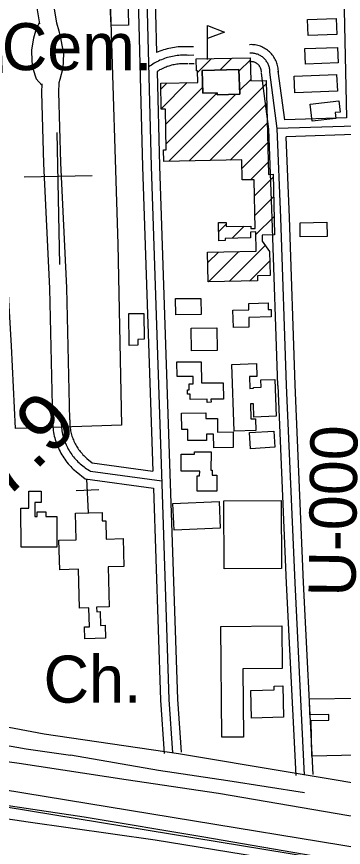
# Model space of a CAD drawing. Extents: x 3508733 to 3546731, y 546897 to 572481.
# Drawn here: x 3525061 to 3525636, y 566055 to 567520 of the extents above; entities that cross this region are included whole.
import ezdxf

# ---------------------------------------------------------------- set-up
doc = ezdxf.new("R2010")
doc.units = 0
for name, color, linetype in [('V-BLDG-OTLN', 7, 'Continuous'), ('V-FLOD-BASE', 7, 'Continuous'), ('V-LEVE-TOET', 7, 'Continuous'), ('V-RIVR-RANG-IDEN', 7, 'Continuous'), ('V-ROAD-CNTR', 7, 'Continuous'), ('V-SITE-OTLN', 7, 'Continuous'), ('V-SITE-OTLN-IDEN', 7, 'Continuous'), ('V-SURV-IDEN', 7, 'Continuous'), ('V-SURV-LINE', 7, 'Continuous'), ('V-TOPO-SHOR', 7, 'Continuous')]:
    doc.layers.add(name, color=color, linetype=linetype)

msp = doc.modelspace()

# ---------------------------------------------------------------- linework, layer by layer
at = {"layer": 'V-BLDG-OTLN'}
for p, q in [((3525397.2, 567444.3), (3525396.9, 567504.3)), ((3525379.4, 567421.6), (3525404, 567446.2)), ((3525419.2, 567426.1), (3525440.1, 567446.9)), ((3525452.5, 567424), (3525472.5, 567444)), ((3525453.5, 567389.6), (3525473.2, 567409.4)), ((3525314.7, 567392.3), (3525325.4, 567402.9)), ((3525315.4, 567357.6), (3525361.4, 567403.7)), ((3525323.3, 567330.1), (3525388.4, 567395.3)), ((3525364.8, 567265.6), (3525500.5, 567401.3)), ((3525324, 567295.5), (3525414.1, 567385.6)), ((3525328.7, 567264.9), (3525447.2, 567383.4)), ((3525400.9, 567266.3), (3525501.4, 567366.8)), ((3525437, 567267), (3525502.3, 567332.3)), ((3525457.8, 567252.5), (3525503.1, 567297.9)), ((3525472.9, 567232.3), (3525504, 567263.4)), ((3525479.9, 567203.9), (3525512.6, 567236.7)), ((3525480.6, 567169.3), (3525513.5, 567202.2)), ((3525482.3, 567135.6), (3525514.4, 567167.7)), ((3525416.8, 567140.8), (3525430.1, 567154.1)), ((3525440.4, 567129.1), (3525461.8, 567150.4)), ((3525434.9, 567052.8), (3525498.7, 567116.6)), ((3525397.5, 567086.2), (3525416.3, 567104.9)), ((3525398.8, 567052.1), (3525452.3, 567105.6)), ((3525470.9, 567053.5), (3525506.8, 567089.4))]:
    msp.add_line(p, q, dxfattribs=at)
for points in [[(3525222.6, 567601.8), (3525262.3, 567602.9), (3525262.9, 567580.8), (3525255.9, 567580.6), (3525258, 567505.1), (3525227.2, 567504.3)], [(3525624.7, 567488.8), (3525574.5, 567487), (3525573.5, 567515.1), (3525623.7, 567516.9)], [(3525396.9, 567504.3), (3525426.9, 567492.9), (3525397, 567481.2)], [(3525627, 567438.5), (3525569.6, 567436.3), (3525568.6, 567463.7), (3525626, 567465.9)], [(3525500.4, 567407.4), (3525504.6, 567241.9), (3525512.5, 567242.1), (3525515.2, 567135.3), (3525493.2, 567134.7), (3525493.5, 567123.8), (3525506.5, 567105.8), (3525507.4, 567063.2), (3525484.9, 567062.8), (3525485.1, 567053.8), (3525398.2, 567052.1), (3525397.1, 567104.6), (3525482.9, 567106.3), (3525482.2, 567140.2), (3525472.7, 567140), (3525472.9, 567129.7), (3525428.4, 567128.8), (3525428.4, 567125.1), (3525417.1, 567124.8), (3525416.5, 567156.7), (3525430, 567157), (3525430.1, 567149.8), (3525473.4, 567150.7), (3525473.5, 567146.5), (3525481.1, 567146.6), (3525479.3, 567232.4), (3525458.2, 567232), (3525457.5, 567267.5), (3525319.9, 567264.7), (3525319.5, 567285.1), (3525324.2, 567285.2), (3525322.8, 567356.8), (3525315.4, 567356.7), (3525314.5, 567402.7), (3525379.7, 567404), (3525379.3, 567424.3), (3525377.4, 567424.2), (3525376.9, 567445.7), (3525472.4, 567447.6), (3525473.3, 567406.8)], [(3525387.5, 567425.1), (3525388.7, 567384.9), (3525414.1, 567385.7), (3525414.2, 567382.4), (3525453.7, 567383.5), (3525452.4, 567427)], [(3525387.5, 567425.1), (3525452.4, 567427), (3525453.7, 567383.5), (3525414.2, 567382.4), (3525414.1, 567385.7), (3525388.7, 567384.9)], [(3525625.8, 567388.4), (3525550.7, 567385.5), (3525549.6, 567415.3), (3525624.6, 567418.1)], [(3525623.2, 567340.5), (3525581.7, 567335.5), (3525578.1, 567365.8), (3525628.5, 567371.8), (3525630.9, 567351.7), (3525622, 567350.7)], [(3525607.8, 567132.4), (3525560.4, 567131.6), (3525560, 567156.5), (3525607.4, 567157.3)], [(3525385.7, 566994.6), (3525341.1, 566994.3), (3525340.9, 567022.7), (3525385.5, 567023)], [(3525509.4, 566990.3), (3525469.7, 566989.2), (3525470.1, 566972.5), (3525442.8, 566971.8), (3525441.9, 567002.1), (3525470, 567002.9), (3525469.7, 567014.3), (3525503.7, 567015.3), (3525504.1, 567003.3), (3525509, 567003.4)], [(3525258.4, 566996.4), (3525285.1, 566996.7), (3525285.5, 566950.9), (3525274.1, 566950.8), (3525274.2, 566940.3), (3525259, 566940.1)], [(3525413.4, 566971.3), (3525414, 566931.3), (3525368.9, 566930.6), (3525368.3, 566970.6)], [(3525386.3, 566874), (3525424.7, 566874.4), (3525425, 566845.5), (3525403.1, 566845.3), (3525403.2, 566839.8), (3525396.3, 566839.7), (3525396.2, 566845.2), (3525366.4, 566844.9), (3525366.3, 566854), (3525361.9, 566853.9), (3525361.8, 566861.9), (3525364.7, 566862), (3525364.6, 566872.4), (3525372, 566872.5), (3525371.9, 566885.4), (3525343.4, 566885.1), (3525343.1, 566911), (3525385.9, 566911.4)], [(3525439.6, 566906.7), (3525483.2, 566908.4), (3525484, 566885.5), (3525471, 566885.1), (3525471.8, 566864.4), (3525478.3, 566864.6), (3525478.3, 566866.1), (3525491.5, 566866.6), (3525491, 566879.2), (3525515.7, 566880.1), (3525518.1, 566815.2), (3525478.7, 566813.8), (3525477.8, 566837), (3525472.6, 566836.8), (3525473.6, 566810.5), (3525481.5, 566810.8), (3525482.2, 566790.3), (3525444, 566788.8)], [(3525395.2, 566772.7), (3525362.4, 566772.3), (3525362.2, 566792.1), (3525351.5, 566791.9), (3525351.1, 566820.5), (3525394.1, 566821.1), (3525394.3, 566811), (3525414.4, 566811.2), (3525414.7, 566787.3), (3525442, 566787.6), (3525442.4, 566760), (3525408, 566759.5), (3525407.6, 566783.7), (3525395.1, 566783.5)], [(3525471.2, 566786.3), (3525514, 566788.9), (3525515.7, 566760.4), (3525472.9, 566757.7)], [(3525383.2, 566718.1), (3525350.6, 566718.1), (3525350.7, 566748.5), (3525374, 566748.5), (3525374, 566752.4), (3525403.2, 566752.3), (3525403.1, 566719.9), (3525405.4, 566719.9), (3525405.4, 566711.1), (3525413.3, 566711.1), (3525413.2, 566683), (3525378.5, 566683), (3525378.6, 566709.9), (3525383.1, 566709.9)], [(3525131.4, 566584.4), (3525068.4, 566584.2), (3525068.2, 566652.8), (3525082.1, 566652.8), (3525082, 566683.2), (3525103.9, 566683.2), (3525103.9, 566662.8), (3525092.5, 566662.8), (3525092.5, 566638.3), (3525096.6, 566638.3), (3525096.6, 566646.7), (3525112.3, 566646.7), (3525112.3, 566638.6), (3525131.3, 566638.6)], [(3525419.6, 566617.6), (3525338, 566614.1), (3525336, 566661.4), (3525417.6, 566664.9)], [(3525426.6, 566545.9), (3525425.8, 566666), (3525526.6, 566666.7), (3525527.5, 566546.6)], [(3525171.3, 566476.8), (3525169.4, 566545.2), (3525136.6, 566544.3), (3525135.2, 566596.4), (3525165.8, 566597.3), (3525164.5, 566644.5), (3525211.2, 566645.7), (3525211.6, 566630.6), (3525217.8, 566630.7), (3525218.7, 566598.5), (3525248.1, 566599.3), (3525249.4, 566550.3), (3525222, 566549.6), (3525223.9, 566479.1), (3525201.5, 566478.5), (3525201.8, 566470.3), (3525207.8, 566470.5), (3525208.5, 566446.1), (3525216.9, 566446.4), (3525217.5, 566423.7), (3525180.7, 566422.7), (3525180.1, 566443.8), (3525188.9, 566444), (3525188, 566477.2)], [(3525420.3, 566444.6), (3525528, 566445.5), (3525528.7, 566370), (3525459.5, 566369.4), (3525460.5, 566249.4), (3525422.1, 566249)], [(3525659.7, 566217.1), (3525580.7, 566215.9), (3525579.8, 566278.6), (3525610.8, 566279.1), (3525610.7, 566289.1), (3525577.4, 566288.6), (3525577, 566316.5), (3525665.4, 566317.9), (3525664.9, 566351.9), (3525680.9, 566352.2), (3525681.2, 566333.6), (3525692.9, 566333.8), (3525693.6, 566290.3), (3525683.3, 566290.1), (3525683.3, 566287.4), (3525666.9, 566287.2), (3525666.9, 566291.4), (3525658.5, 566291.2)], [(3525531.2, 566284.3), (3525474.3, 566282.8), (3525473.1, 566331.4), (3525514.5, 566332.4), (3525514.3, 566339.2), (3525529.8, 566339.6)]]:
    msp.add_lwpolyline(points, close=True, dxfattribs=at)
at = {"layer": 'V-FLOD-BASE'}
msp.add_lwpolyline([(3527002.6, 565995.7), (3526928.9, 566006.7), (3526890.6, 566009.2), (3526863.9, 566009.4), (3526827.7, 566007.1), (3526794.8, 566000.6), (3526742.7, 565989.5), (3526684.4, 565970.3), (3526606.1, 565938.2), (3526534.1, 565910.9), (3526495.6, 565894.9), (3526466.9, 565891.1), (3526442.9, 565890), (3526394.5, 565901.4), (3526294.9, 565918.8), (3526170, 565939.2), (3526009.6, 565966.9), (3525802.8, 566002.5), (3525581.7, 566039.6), (3525390.6, 566073), (3525179.7, 566107.9), (3524998.1, 566135.1), (3524872.1, 566156.4)], dxfattribs=at)
at = {"layer": 'V-LEVE-TOET'}
msp.add_line((3524916.6, 566224.7), (3525065.2, 566203.2), dxfattribs=at)
for points in [[(3525065.2, 566203.2), (3525253.6, 566174.6), (3525416.1, 566150.4), (3525646.1, 566111.1), (3525859.8, 566078.2), (3526102.7, 566038.1), (3526328.6, 565997.6), (3526390.1, 565989.4), (3526435.9, 565988.9), (3526487.9, 565995.9), (3526511.2, 566001.2), (3526586, 566023.6), (3526725.9, 566073.5), (3526776.7, 566087.3), (3526828.7, 566095), (3526897.8, 566101.1)], [(3524899.4, 566127), (3525081, 566099.9), (3525304.9, 566068.2), (3525485.1, 566038.4)]]:
    msp.add_lwpolyline(points, dxfattribs=at)
at = {"layer": 'V-ROAD-CNTR'}
for points in [[(3525626.5, 568407.7), (3525646.7, 567804), (3525657.4, 567327.1), (3525520, 567322.8)], [(3525612, 568391.9), (3525631.7, 567803.6), (3525642.1, 567341.6), (3525533.1, 567338.2)], [(3525265.1, 567832.3), (3525271.9, 567664.4), (3525282.6, 567255.2), (3525300.7, 566718.5)], [(3525280.1, 567833), (3525286.9, 567664.9), (3525297.6, 567255.6), (3525316.4, 566696.1), (3525328.9, 566315.3), (3525335.5, 566221.3)], [(3525295.1, 567833.6), (3525301.9, 567665.4), (3525307.3, 567456.9)], [(3525125.8, 567540.4), (3525130.7, 567509.3), (3525135.3, 567495.3), (3525138.8, 567479.1), (3525143, 567454.6), (3525141.9, 567429.4), (3525136.5, 567409.2), (3525134.9, 567403.5), (3525134.7, 567386.7), (3525138.2, 567262.3), (3525148.3, 567041.5), (3525154, 566808.6)], [(3525096.1, 567535.7), (3525100.7, 567507.2)], [(3525100.4, 567508.3), (3525095.2, 567498.6), (3525090.2, 567481.9), (3525086.9, 567461.7), (3525087.5, 567441.1), (3525089, 567428.6), (3525095.2, 567410.3), (3525105.2, 567399.4)], [(3525364.9, 567466.7), (3525361.8, 567466.9), (3525358.5, 567467), (3525355.2, 567467), (3525351.9, 567467), (3525348.6, 567466.8), (3525345.3, 567466.6), (3525342, 567466.2), (3525338.7, 567465.8), (3525335.5, 567465.3), (3525332.2, 567464.7), (3525329, 567464), (3525325.8, 567463.2), (3525322.6, 567462.3), (3525319.4, 567461.4), (3525316.3, 567460.3), (3525313.2, 567459.2), (3525307.3, 567456.9)], [(3525372.2, 567467), (3525363.4, 567466.7)], [(3525522, 567422.3), (3525521.9, 567424.3), (3525521.8, 567426.7), (3525521.5, 567429), (3525521.1, 567431.4), (3525520.6, 567433.7), (3525520, 567436), (3525519.3, 567438.2), (3525518.4, 567440.4), (3525517.5, 567442.6), (3525516.4, 567444.7), (3525515.3, 567446.8), (3525514, 567448.8), (3525512.7, 567450.8), (3525511.2, 567452.6), (3525509.7, 567454.5), (3525508.1, 567456.2), (3525506.4, 567457.8), (3525504.6, 567459.4), (3525502.7, 567460.9), (3525500.8, 567462.3), (3525498.8, 567463.5), (3525496.8, 567464.7), (3525494.7, 567465.8), (3525492.5, 567466.8), (3525490.3, 567467.7), (3525488.1, 567468.4), (3525485.8, 567469.1), (3525483.5, 567469.6), (3525481.2, 567470.1), (3525478.8, 567470.4), (3525476.5, 567470.6), (3525474.1, 567470.7), (3525471.8, 567470.6), (3525471, 567470.6)], [(3525363.9, 567451.7), (3525361, 567451.9), (3525358.2, 567452), (3525355.3, 567452), (3525352.4, 567452), (3525349.5, 567451.9), (3525346.6, 567451.6), (3525343.7, 567451.3), (3525340.9, 567451), (3525338, 567450.5), (3525335.2, 567450), (3525332.4, 567449.4), (3525329.6, 567448.7), (3525326.8, 567447.9), (3525324, 567447.1), (3525321.3, 567446.2), (3525318.6, 567445.2), (3525315.9, 567444.1), (3525313.2, 567443), (3525310.6, 567441.8), (3525308, 567440.5), (3525305.5, 567439.1), (3525302.9, 567437.7), (3525300.5, 567436.2), (3525298.1, 567434.6), (3525295.7, 567433), (3525293.3, 567431.3), (3525293, 567431)], [(3525372.8, 567452), (3525363.9, 567451.7)], [(3525507, 567422), (3525506.9, 567423.7), (3525506.8, 567425.3), (3525506.6, 567426.9), (3525506.4, 567428.5), (3525506, 567430.1), (3525505.6, 567431.7), (3525505.1, 567433.3), (3525504.5, 567434.8), (3525503.9, 567436.3), (3525503.1, 567437.8), (3525502.3, 567439.2), (3525501.5, 567440.6), (3525500.5, 567441.9), (3525499.6, 567443.2), (3525498.5, 567444.5), (3525497.4, 567445.7), (3525496.2, 567446.8), (3525495, 567447.9), (3525493.7, 567448.9), (3525492.4, 567449.9), (3525491, 567450.7), (3525489.6, 567451.6), (3525488.1, 567452.3), (3525486.6, 567453), (3525485.1, 567453.6), (3525483.6, 567454.1), (3525482, 567454.6), (3525480.4, 567454.9), (3525478.8, 567455.2), (3525477.2, 567455.5), (3525475.6, 567455.6), (3525473.9, 567455.7), (3525472.3, 567455.6), (3525471.7, 567455.6)], [(3525363, 567436.8), (3525360.3, 567436.9), (3525357.8, 567437), (3525355.3, 567437), (3525352.9, 567437), (3525350.4, 567436.9), (3525347.9, 567436.7), (3525345.5, 567436.4), (3525343, 567436.1), (3525340.6, 567435.7), (3525338.1, 567435.3), (3525335.7, 567434.8), (3525333.3, 567434.2), (3525330.9, 567433.5), (3525328.6, 567432.8), (3525326.2, 567432), (3525323.9, 567431.2), (3525321.6, 567430.2), (3525319.3, 567429.3), (3525317.1, 567428.2), (3525314.9, 567427.1), (3525312.7, 567426), (3525310.5, 567424.7), (3525308.2, 567423.3)], [(3525373.3, 567437.1), (3525364.5, 567436.7)], [(3525492, 567421.8), (3525491.9, 567423), (3525491.9, 567423.9), (3525491.8, 567424.8), (3525491.6, 567425.7), (3525491.4, 567426.6), (3525491.2, 567427.5), (3525490.9, 567428.3), (3525490.6, 567429.2), (3525490.3, 567430), (3525489.9, 567430.8), (3525489.4, 567431.6), (3525488.9, 567432.3), (3525488.4, 567433.1), (3525487.9, 567433.8), (3525487.3, 567434.5), (3525486.7, 567435.1), (3525486, 567435.8), (3525485.4, 567436.4), (3525484.7, 567436.9), (3525483.9, 567437.5), (3525483.2, 567437.9), (3525482.4, 567438.4), (3525481.6, 567438.8), (3525480.8, 567439.2), (3525479.9, 567439.5), (3525479.1, 567439.8), (3525478.2, 567440.1), (3525477.3, 567440.3), (3525476.4, 567440.4), (3525475.6, 567440.5), (3525474.7, 567440.6), (3525473.8, 567440.7), (3525472.7, 567440.6), (3525472.4, 567440.6)], [(3525308.2, 567423.3), (3525312.6, 567256.1), (3525331.4, 566696.6), (3525343.9, 566316), (3525350.4, 566222.4)], [(3525536.2, 566870.1), (3525526.2, 567165.1), (3525520, 567322.8), (3525507, 567422)], [(3525533.1, 567338.2), (3525521.8, 567424)], [(3525521.2, 566869.6), (3525511.2, 567164.6), (3525505.1, 567321.5), (3525492.1, 567420.1)], [(3525104.8, 567401.5), (3525104.7, 567386.4), (3525108.2, 567261.2), (3525118.3, 567040.5), (3525124, 566807.8)], [(3525672.7, 567313), (3525672.7, 567312.6), (3525535.6, 567308.3)], [(3525551.2, 566870.6), (3525541.2, 567165.7), (3525535.6, 567308.3)], [(3525553.1, 566181.7), (3525536.4, 566520.7), (3525521.3, 566869.4)], [(3525568.1, 566182.4), (3525551.4, 566521.4), (3525536.2, 566870.1)], [(3525583.1, 566183.2), (3525566.3, 566522.1), (3525551.2, 566870.7)], [(3525124.3, 566809.1), (3525124.2, 566806.1), (3525124.2, 566802.8), (3525124.4, 566799.6), (3525124.6, 566796.3), (3525124.9, 566793.1), (3525125.3, 566789.9), (3525125.8, 566786.7), (3525126.4, 566783.5), (3525127, 566780.3), (3525127.8, 566777.2), (3525128.7, 566774), (3525129.6, 566770.9), (3525130.6, 566767.9), (3525131.7, 566764.8), (3525132.9, 566761.8), (3525134.2, 566758.8), (3525135.6, 566755.9), (3525137.1, 566753), (3525138.6, 566750.1), (3525140.2, 566747.3), (3525141.9, 566744.6), (3525143.7, 566741.8), (3525145.5, 566739.2), (3525147.5, 566736.6), (3525149.4, 566734), (3525151.5, 566731.5), (3525153.7, 566729.1), (3525155.9, 566726.7), (3525158.1, 566724.4), (3525160.5, 566722.1), (3525162.9, 566720), (3525165.3, 566717.8), (3525181.6, 566704.7)], [(3525139.3, 566808.8), (3525139.2, 566806), (3525139.2, 566803.2), (3525139.4, 566800.4), (3525139.5, 566797.6), (3525139.8, 566794.8), (3525140.2, 566792), (3525140.6, 566789.2), (3525141.1, 566786.4), (3525141.7, 566783.6), (3525142.3, 566780.9), (3525143.1, 566778.2), (3525143.9, 566775.5), (3525144.8, 566772.8), (3525145.8, 566770.2), (3525146.8, 566767.6), (3525147.9, 566765), (3525149.1, 566762.4), (3525150.4, 566759.9), (3525151.7, 566757.4), (3525153.1, 566755), (3525154.6, 566752.6), (3525156.1, 566750.2), (3525157.7, 566747.9), (3525159.4, 566745.6), (3525161.1, 566743.4), (3525162.9, 566741.2), (3525164.8, 566739.1), (3525166.7, 566737.1), (3525168.7, 566735), (3525170.7, 566733.1), (3525172.8, 566731.2), (3525174.9, 566729.4), (3525177.1, 566727.6), (3525179.4, 566725.9), (3525181.7, 566724.2), (3525184, 566722.7), (3525186.4, 566721.1), (3525188.8, 566719.7), (3525190.9, 566718.5)], [(3525154.3, 566808.6), (3525154.2, 566805.9), (3525154.2, 566803.6), (3525154.3, 566801.2), (3525154.5, 566798.8), (3525154.7, 566796.4), (3525155, 566794), (3525155.4, 566791.7), (3525155.8, 566789.3), (3525156.3, 566787), (3525156.9, 566784.6), (3525157.5, 566782.3), (3525158.2, 566780.1), (3525159, 566777.8), (3525159.8, 566775.5), (3525160.7, 566773.3), (3525161.6, 566771.1), (3525162.6, 566769), (3525163.7, 566766.8), (3525164.8, 566764.7), (3525166, 566762.6), (3525167.3, 566760.6), (3525168.6, 566758.6), (3525169.9, 566756.6), (3525171.4, 566754.7), (3525172.8, 566752.8), (3525174.3, 566751), (3525175.9, 566749.2), (3525177.6, 566747.4), (3525179.2, 566745.7), (3525181, 566744.1), (3525182.7, 566742.5), (3525184.5, 566740.9), (3525194, 566733.3)], [(3525194, 566733.3), (3525300.7, 566718.5)], [(3525190.9, 566718.5), (3525316.3, 566701.2)], [(3525181.6, 566704.7), (3525301.7, 566688.1)], [(3525301.7, 566688.1), (3525313.9, 566314.5), (3525320.5, 566220.3)], [(3526295, 566063), (3526151.1, 566087), (3525732.2, 566154.8), (3525346, 566219.8), (3525109, 566254.5), (3524971.9, 566280.2), (3524747.2, 566314.6)]]:
    msp.add_lwpolyline(points, dxfattribs=at)
at = {"layer": 'V-SITE-OTLN'}
for p, q in [((3525136.9, 567083), (3525132.2, 567315.4)), ((3525193.8, 567239.2), (3525073.7, 567236.7)), ((3525187.1, 566644.7), (3525184.6, 566704.6)), ((3525205.4, 566685.5), (3525165.4, 566683.8))]:
    msp.add_line(p, q, dxfattribs=at)
msp.add_lwpolyline([(3525123.3, 566795.5), (3525058.9, 566793.6), (3525051.5, 566939.6), (3525045.1, 567050.7), (3525035.2, 567425.6), (3525027.9, 567615.1), (3524999.1, 568387.4), (3525103, 568389.8), (3525106, 568125.4), (3525128.5, 568123), (3525136.1, 567977.2), (3525211.8, 567977.5), (3525239, 567118.6), (3525245.3, 566799.2)], close=True, dxfattribs=at)
at = {"layer": 'V-SURV-LINE'}
for points in [[(3524549.8, 566236.9), (3526455.7, 565924)], [(3526450.9, 565894.3), (3524545, 566207.3)]]:
    msp.add_lwpolyline(points, dxfattribs=at)
at = {"layer": 'V-TOPO-SHOR'}
for points in [[(3524704.5, 566290.2), (3524760.8, 566281.2), (3524790.7, 566277.1), (3524830.2, 566268.7), (3524890.8, 566258.1), (3524970.4, 566246.9), (3525007.8, 566240.9), (3525077.2, 566228.8), (3525155.4, 566217.2)], [(3525568.1, 566150.9), (3525433, 566172.1), (3525310.8, 566190.4), (3525155.4, 566217.2)]]:
    msp.add_lwpolyline(points, dxfattribs=at)

# ---------------------------------------------------------------- texts
at = {"layer": 'V-RIVR-RANG-IDEN'}
msp.add_text('U-000', height=83, rotation=89.2633, dxfattribs=at).set_placement((3525657.8, 566496.5))
at = {"layer": 'V-SITE-OTLN-IDEN'}
for s, p in [('Cem.', (3525034.5, 567425.6)), ('Ch.', (3525108.1, 566310))]:
    msp.add_text(s, height=83, dxfattribs=at).set_placement(p)
at = {"layer": 'V-SURV-IDEN'}
msp.add_text('4641+07.9', height=100, rotation=44.4791, dxfattribs=at).set_placement((3524719.2, 566350.4))

doc.saveas('drawing.dxf')
